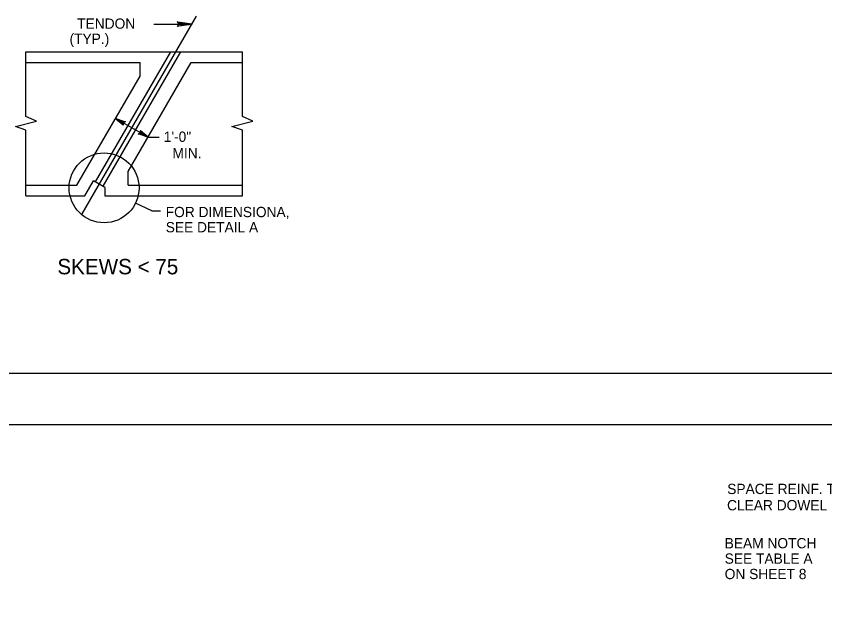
# Model space of a CAD drawing. Extents: x 639331 to 643089, y 299088 to 300975.
# Drawn here: x 640750.5 to 640986.5, y 300796.4 to 300973.9 of the extents above; entities that cross this region are included whole.
import ezdxf

# ---------------------------------------------------------------- set-up
doc = ezdxf.new("R2010")
doc.units = 0
doc.layers.add('1', color=7, linetype='Continuous')
doc.layers.add('PLT-BNDY', color=7, linetype='Continuous')

msp = doc.modelspace()

# ---------------------------------------------------------------- linework, layer by layer
at = {"layer": '1'}
for p, q in [((640769.74, 300916.22), (640803.06, 300973.93)), ((640790.67, 300971.63), (640801.73, 300971.63)), ((640753.31, 300963.54), (640816.49, 300963.54)), ((640753.31, 300944.65), (640753.31, 300963.54)), ((640773.64, 300925.5), (640795.6, 300963.54)), ((640775.83, 300924.23), (640798.52, 300963.54)), ((640816.49, 300944.65), (640816.49, 300963.54)), ((640753.31, 300960.41), (640786.62, 300960.41)), ((640783.18, 300928.54), (640801.58, 300960.41)), ((640786.62, 300956.41), (640786.62, 300960.41)), ((640801.58, 300960.41), (640816.49, 300960.41)), ((640768.22, 300924.54), (640786.62, 300956.41)), ((640788.97, 300938.57), (640779.48, 300944.05)), ((640753.31, 300921.41), (640753.31, 300940.61)), ((640816.49, 300921.41), (640816.49, 300940.61)), ((640788.97, 300938.57), (640792.21, 300938.57)), ((640783.18, 300924.54), (640783.18, 300928.54)), ((640753.31, 300924.54), (640768.22, 300924.54)), ((640770.55, 300921.41), (640773.09, 300925.81)), ((640776.37, 300923.92), (640773.09, 300925.81)), ((640776.37, 300923.92), (640776.37, 300921.41)), ((640783.18, 300924.54), (640816.49, 300924.54)), ((640753.31, 300921.41), (640770.55, 300921.41)), ((640776.37, 300921.41), (640816.49, 300921.41)), ((640790.08, 300917.05), (640785.32, 300919.34)), ((640790.08, 300917.05), (640792.63, 300917.05)), ((640592.06, 300854.66), (641378.06, 300854.66))]:
    msp.add_line(p, q, dxfattribs=at)
for points in [[(640797.65, 300972.14), (640797.8, 300971.85), (640801.73, 300971.63), (640797.65, 300972.14), (640797.44, 300972.32), (640801.73, 300971.63), (640797.8, 300971.44), (640797.66, 300971.14), (640801.73, 300971.63), (640797.44, 300970.95), (640797.66, 300971.14)], [(640753.31, 300940.61), (640750.24, 300941.66), (640756.37, 300943.29), (640753.31, 300944.65)], [(640779.48, 300944.05), (640782.35, 300943.04), (640782.21, 300943.03), (640782.07, 300943.02), (640781.97, 300942.96), (640781.87, 300942.9), (640781.8, 300942.83), (640781.74, 300942.75), (640781.7, 300942.65), (640781.67, 300942.56), (640781.67, 300942.44), (640781.67, 300942.33), (640781.73, 300942.2), (640781.79, 300942.07), (640779.48, 300944.05), (640781.73, 300942.2), (640781.67, 300942.33), (640779.48, 300944.05), (640781.67, 300942.44), (640781.67, 300942.56), (640779.48, 300944.05), (640781.7, 300942.65), (640781.74, 300942.75), (640779.48, 300944.05), (640781.8, 300942.83), (640781.87, 300942.9), (640779.48, 300944.05), (640781.97, 300942.96), (640782.07, 300943.02), (640779.48, 300944.05), (640782.21, 300943.03)], [(640816.49, 300940.61), (640813.43, 300941.66), (640819.56, 300943.29), (640816.49, 300944.65)], [(640788.97, 300938.57), (640786.11, 300939.58), (640786.25, 300939.59), (640786.39, 300939.6), (640786.49, 300939.66), (640786.59, 300939.72), (640786.65, 300939.79), (640786.72, 300939.87), (640786.75, 300939.97), (640786.79, 300940.06), (640786.79, 300940.18), (640786.79, 300940.3), (640786.73, 300940.42), (640786.67, 300940.55), (640788.97, 300938.57), (640786.73, 300940.42), (640786.79, 300940.3), (640788.97, 300938.57), (640786.79, 300940.18), (640786.79, 300940.06), (640788.97, 300938.57), (640786.75, 300939.97), (640786.72, 300939.87), (640788.97, 300938.57), (640786.65, 300939.79), (640786.59, 300939.72), (640788.97, 300938.57), (640786.49, 300939.66), (640786.39, 300939.6), (640788.97, 300938.57), (640786.25, 300939.59)]]:
    msp.add_lwpolyline(points, dxfattribs=at)
msp.add_circle((640776.14, 300923.78), 10.2, dxfattribs=at)
at = {"layer": 'PLT-BNDY'}
msp.add_lwpolyline([(640552.06, 300869.66), (641393.06, 300869.66), (641393.06, 300275.66), (640552.06, 300275.66)], close=True, dxfattribs=at)

# ---------------------------------------------------------------- texts
at = {"layer": '1'}
for s, height, p in [('  TENDON', 3, (640766.06, 300970.26)), ('(TYP.)', 3, (640766.06, 300965.82)), ('1\'-0"', 3, (640793.56, 300937.22)), ('MIN.', 3, (640796.1, 300932.42)), ('FOR DIMENSIONA,', 3, (640794.13, 300915.23)), ('SEE DETAIL A', 3, (640794.13, 300910.79)), ('SKEWS < 75', 4.5, (640762.51, 300898.53)), ('SPACE REINF. TO', 3, (640957.99, 300834.35)), ('CLEAR DOWEL HOLE', 3, (640957.94, 300829.59)), ('BEAM NOTCH', 3, (640957.25, 300818.5)), ('SEE TABLE A', 3, (640957.25, 300814)), ('ON SHEET 8', 3, (640957.25, 300809.5))]:
    msp.add_text(s, height=height, dxfattribs=at).set_placement(p)

doc.saveas('drawing.dxf')
